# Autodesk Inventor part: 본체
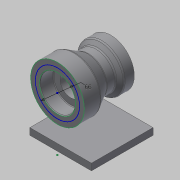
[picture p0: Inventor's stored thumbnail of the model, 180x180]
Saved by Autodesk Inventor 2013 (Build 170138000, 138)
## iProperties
Created: 2019-01
Part Number: 본체
Material: Generic
Document SubType Name: Modeling
Designer: Administrator
Density: 1 g/cm^3
Author: Administrator
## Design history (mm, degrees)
sketch "스케치1"
  geometry: L1 (-46, 46)-(46, 46); L2 (46, 46)-(46, -46); L3 (46, -46)-(-46, -46); L4 (-46, -46)-(-46, 46); 3 further points
  constraints: 8 end point, 2 midpoint, 2 parallel, 1 horizontal, 1 horizontal alignment, 1 perpendicular, 1 vertical alignment
  dimensions: "d0" = 92 distance between parallel lines of L2 L4; "d2" = 92 distance between parallel lines of L3 L1
extrude "돌출1" new body sketch "스케치1" distance "d3" = 10; taper "d4" = 0 deg
sketch "스케치2"
  geometry: L1 (-51, 80)-(29, 80); L2 (46, 0)-(-46, 0) reference; L3 (-46, 0)-(-46, 10) reference; L4 (-51, 106)-(-51, 120); L5 (-51, 120)-(-26, 120); L6 (-26, 120)-(-5.215, 108); L7 (-5.215, 108)-(8.126, 108); L8 (8.126, 108)-(14, 115); L9 (14, 115)-(29, 115); L10 (29, 115)-(29, 100); L11 (-51, 106)-(-31, 106); L12 (-31, 106)-(-31, 96); L13 (-31, 96)-(12, 96); L14 (12, 96)-(12, 100); L15 (12, 100)-(29, 100); 1 further point
  constraints: 26 end point, 7 parallel, 3 perpendicular, 2 vertical alignment, 1 horizontal
  dimensions: "d5" = 80 distance between parallel lines of L2 L1; "d6" = 80 distance of L1.end L1.start; "d7" = 5 distance from line of L3 L1.start; "d8" = 17 distance between parallel lines of L10 L14; "d9" = 20 distance between parallel lines of L12 L4; "d10" = 56 diameter of L7 L1; "d12" = 80 diameter of L5 L1; "d13" = 70 diameter of L9 L1; "d14" = 50 deg angle of L7 L8; "d15" = 30 deg angle of L7 L6; "d16" = 25 distance of L4.end L5.end; "d17" = 15 distance of L9.end L8.end; "d18" = 40 diameter of L15 L1; "d19" = 32 diameter of L13 L1; "d20" = 52 diameter of L11 L1
revolve "회전1" sketch "스케치2" stored, may be unused: angle "d21" = 90 deg
fillet "모깎기1" dims "d22" = 1
fillet "모깎기2" dims "d23" = 0.6
chamfer "모따기1" distance "d24" = 1; stored, may be unused: second distance "d25" = 2, angle "d26" = 45 deg
fillet "모깎기3" dims "d27" = 3
sketch "스케치3"
  geometry: C1 r 40 at (0, 0) reference; C2 r 27 at (0, 0) reference; C3 r 33 at (0, 0); 1 further point
  constraints: 1 centre point, 1 coincident
  dimensions: "d28" = 66 diameter of C3
node "솔리드1"
